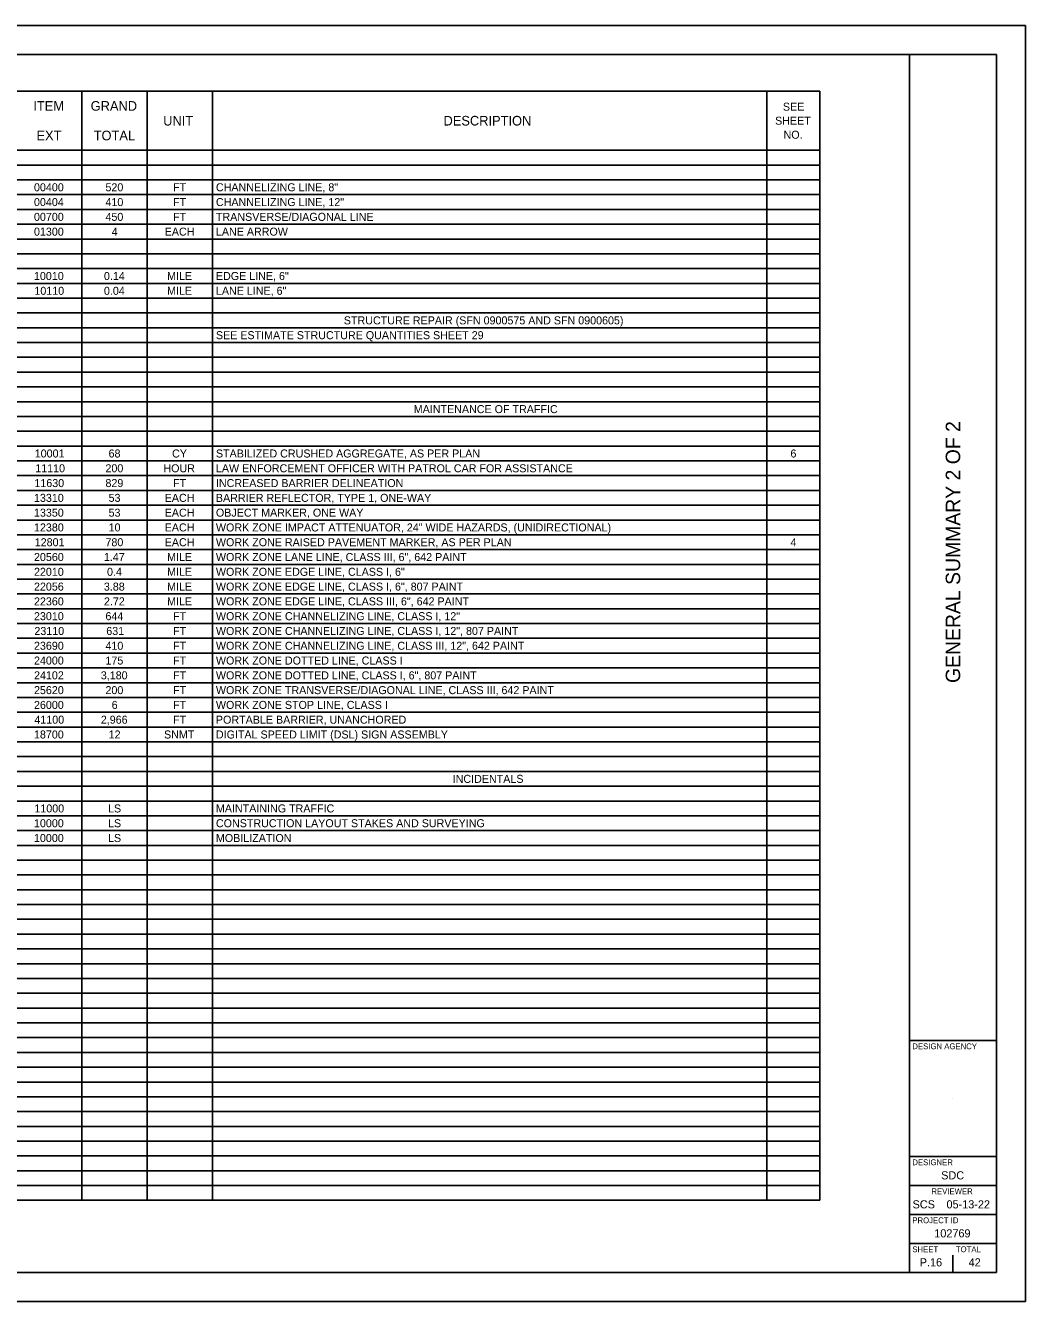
# Model space of a CAD drawing. Extents: x 0 to 34, y 0 to 22.
# Drawn here: x 16.76 to 34, y 0 to 22 of the extents above; entities that cross this region are included whole.
import ezdxf

# ---------------------------------------------------------------- set-up
doc = ezdxf.new("R2010")
doc.units = 0
for name, color, linetype in [('SH_Border', 7, 'Continuous'), ('SH_Cut_Line', 7, 'Continuous'), ('SH_Data', 7, 'Continuous'), ('SH_Text', 7, 'Continuous')]:
    doc.layers.add(name, color=color, linetype=linetype)

msp = doc.modelspace()

# ---------------------------------------------------------------- linework, layer by layer
at = {"layer": 'SH_Border'}
for p, q in [((32, 0.5), (32, 21.5)), ((32, 4.5), (33.5, 4.5)), ((32, 2.5), (33.5, 2.5)), ((32, 2), (33.5, 2)), ((32, 1.5), (33.5, 1.5)), ((32, 1), (33.5, 1))]:
    msp.add_line(p, q, dxfattribs=at)
msp.add_lwpolyline([(1.5, 21.5), (33.5, 21.5), (33.5, 0.5), (1.5, 0.5)], close=True, dxfattribs=at)
at = {"layer": 'SH_Cut_Line'}
msp.add_lwpolyline([(0, 0), (34, 0), (34, 22), (0, 22)], close=True, dxfattribs=at)
at = {"layer": 'SH_Data'}
for p, q in [((32.75, 3.5), (32.75, 3.5)), ((32.375, 0.675), (32.375, 0.675)), ((32.75, 0.5), (32.75, 0.8))]:
    msp.add_line(p, q, dxfattribs=at)
at = {"layer": 'SH_Text'}
for p, q in [((2.676, 20.869), (30.456, 20.869)), ((17.736, 20.869), (17.736, 1.744)), ((18.861, 20.869), (18.861, 1.744)), ((19.986, 20.869), (19.986, 1.744)), ((29.541, 20.869), (29.541, 1.744)), ((30.456, 20.869), (30.456, 1.744)), ((2.676, 19.849), (30.456, 19.849)), ((2.676, 19.594), (30.456, 19.594)), ((2.676, 19.339), (30.456, 19.339)), ((2.676, 19.084), (30.456, 19.084)), ((2.676, 18.829), (30.456, 18.829)), ((2.676, 18.574), (30.456, 18.574)), ((2.676, 18.319), (30.456, 18.319)), ((2.676, 18.064), (30.456, 18.064)), ((2.676, 17.809), (30.456, 17.809)), ((2.676, 17.554), (30.456, 17.554)), ((2.676, 17.299), (30.456, 17.299)), ((2.676, 17.044), (30.456, 17.044)), ((2.676, 16.789), (30.456, 16.789)), ((2.676, 16.534), (30.456, 16.534)), ((2.676, 16.279), (30.456, 16.279)), ((2.676, 16.024), (30.456, 16.024)), ((2.676, 15.769), (30.456, 15.769)), ((2.676, 15.514), (30.456, 15.514)), ((2.676, 15.259), (30.456, 15.259)), ((2.676, 15.004), (30.456, 15.004)), ((2.676, 14.749), (30.456, 14.749)), ((2.676, 14.494), (30.456, 14.494)), ((2.676, 14.239), (30.456, 14.239)), ((2.676, 13.984), (30.456, 13.984)), ((2.676, 13.729), (30.456, 13.729)), ((2.676, 13.474), (30.456, 13.474)), ((2.676, 13.219), (30.456, 13.219)), ((2.676, 12.964), (30.456, 12.964)), ((2.676, 12.709), (30.456, 12.709)), ((2.676, 12.454), (30.456, 12.454)), ((2.676, 12.199), (30.456, 12.199)), ((2.676, 11.944), (30.456, 11.944)), ((2.676, 11.689), (30.456, 11.689)), ((2.676, 11.434), (30.456, 11.434)), ((2.676, 11.179), (30.456, 11.179)), ((2.676, 10.924), (30.456, 10.924)), ((2.676, 10.669), (30.456, 10.669)), ((2.676, 10.414), (30.456, 10.414)), ((2.676, 10.159), (30.456, 10.159)), ((2.676, 9.904), (30.456, 9.904)), ((2.676, 9.649), (30.456, 9.649)), ((2.676, 9.394), (30.456, 9.394)), ((2.676, 9.139), (30.456, 9.139)), ((2.676, 8.884), (30.456, 8.884)), ((2.676, 8.629), (30.456, 8.629)), ((2.676, 8.374), (30.456, 8.374)), ((2.676, 8.119), (30.456, 8.119)), ((2.676, 7.864), (30.456, 7.864)), ((2.676, 7.609), (30.456, 7.609)), ((2.676, 7.354), (30.456, 7.354)), ((2.676, 7.099), (30.456, 7.099)), ((2.676, 6.844), (30.456, 6.844)), ((2.676, 6.589), (30.456, 6.589)), ((2.676, 6.334), (30.456, 6.334)), ((2.676, 6.079), (30.456, 6.079)), ((2.676, 5.824), (30.456, 5.824)), ((2.676, 5.569), (30.456, 5.569)), ((2.676, 5.314), (30.456, 5.314)), ((2.676, 5.059), (30.456, 5.059)), ((2.676, 4.804), (30.456, 4.804)), ((2.676, 4.549), (30.456, 4.549)), ((2.676, 4.294), (30.456, 4.294)), ((2.676, 4.039), (30.456, 4.039)), ((2.676, 3.784), (30.456, 3.784)), ((2.676, 3.529), (30.456, 3.529)), ((2.676, 3.274), (30.456, 3.274)), ((2.676, 3.019), (30.456, 3.019)), ((2.676, 2.764), (30.456, 2.764)), ((2.676, 2.509), (30.456, 2.509)), ((2.676, 2.254), (30.456, 2.254)), ((2.676, 1.999), (30.456, 1.999)), ((2.676, 1.744), (30.456, 1.744))]:
    msp.add_line(p, q, dxfattribs=at)

# ---------------------------------------------------------------- texts
at = {"layer": 'SH_Data'}
msp.add_text('GENERAL SUMMARY 2 OF 2', height=0.25, rotation=90, dxfattribs=at).set_placement((32.875, 10.664))
for s, height, p in [('DESIGN AGENCY', 0.1, (32.05, 4.35)), ('DESIGNER', 0.1, (32.05, 2.35)), ('SDC', 0.14, (32.547, 2.105)), ('REVIEWER', 0.1, (32.378, 1.85)), ('SCS', 0.14, (32.054, 1.605)), ('05-13-22', 0.14, (32.639, 1.605)), ('PROJECT ID', 0.1, (32.05, 1.35)), ('102769', 0.14, (32.428, 1.105)), ('SHEET', 0.1, (32.05, 0.85)), ('TOTAL', 0.1, (32.8, 0.85)), ('P.16', 0.14, (32.178, 0.605)), ('42', 0.14, (33.021, 0.605))]:
    msp.add_text(s, height=height, dxfattribs=at).set_placement(p)
at = {"layer": 'SH_Text'}
for s, height, p in [('ITEM', 0.1656, (16.899, 20.531)), ('GRAND', 0.1656, (17.887, 20.531)), ('SEE ', 0.138, (29.819, 20.531)), ('UNIT', 0.1656, (19.137, 20.276)), ('DESCRIPTION', 0.1656, (23.969, 20.276)), ('SHEET ', 0.138, (29.684, 20.29)), ('EXT', 0.1656, (16.953, 20.021)), ('TOTAL', 0.1656, (17.939, 20.021)), ('NO.', 0.138, (29.83, 20.048)), ('00400', 0.138, (16.91, 19.142)), ('520', 0.138, (18.142, 19.142)), ('FT', 0.138, (19.308, 19.142)), ('CHANNELIZING LINE, 8"', 0.138, (20.046, 19.142)), ('00404', 0.138, (16.91, 18.887)), ('410', 0.138, (18.142, 18.887)), ('FT', 0.138, (19.308, 18.887)), ('CHANNELIZING LINE, 12"', 0.138, (20.046, 18.887)), ('00700', 0.138, (16.91, 18.632)), ('450', 0.138, (18.142, 18.632)), ('FT', 0.138, (19.308, 18.632)), ('TRANSVERSE/DIAGONAL LINE', 0.138, (20.046, 18.632)), ('01300', 0.138, (16.91, 18.377)), ('4', 0.138, (18.25, 18.377)), ('EACH', 0.138, (19.163, 18.377)), ('LANE ARROW', 0.138, (20.046, 18.377)), ('10010', 0.138, (16.91, 17.612)), ('0.14', 0.138, (18.116, 17.612)), ('MILE', 0.138, (19.204, 17.612)), ('EDGE LINE, 6"', 0.138, (20.046, 17.612)), ('10110', 0.138, (16.917, 17.357)), ('0.04', 0.138, (18.116, 17.357)), ('MILE', 0.138, (19.204, 17.357)), ('LANE LINE, 6"', 0.138, (20.046, 17.357)), ('STRUCTURE REPAIR (SFN 0900575 AND SFN 0900605)', 0.138, (22.251, 16.847)), ('SEE ESTIMATE STRUCTURE QUANTITIES SHEET 29', 0.138, (20.046, 16.592)), ('MAINTENANCE OF TRAFFIC', 0.138, (23.456, 15.317)), ('10001', 0.138, (16.923, 14.552)), ('68', 0.138, (18.196, 14.552)), ('CY', 0.138, (19.29, 14.552)), ('STABILIZED CRUSHED AGGREGATE, AS PER PLAN', 0.138, (20.046, 14.552)), ('6', 0.138, (29.949, 14.552)), ('11110', 0.138, (16.932, 14.297)), ('200', 0.138, (18.142, 14.297)), ('HOUR', 0.138, (19.141, 14.297)), ('LAW ENFORCEMENT OFFICER WITH PATROL CAR FOR ASSISTANCE', 0.138, (20.046, 14.297)), ('11630', 0.138, (16.917, 14.042)), ('829', 0.138, (18.142, 14.042)), ('FT', 0.138, (19.308, 14.042)), ('INCREASED BARRIER DELINEATION', 0.138, (20.046, 14.042)), ('13310', 0.138, (16.91, 13.787)), ('53', 0.138, (18.196, 13.787)), ('EACH', 0.138, (19.163, 13.787)), ('BARRIER REFLECTOR, TYPE 1, ONE-WAY', 0.138, (20.046, 13.787)), ('13350', 0.138, (16.91, 13.532)), ('53', 0.138, (18.196, 13.532)), ('EACH', 0.138, (19.163, 13.532)), ('OBJECT MARKER, ONE WAY', 0.138, (20.046, 13.532)), ('WORK ZONE IMPACT ATTENUATOR, 24" WIDE HAZARDS, (UNIDIRECTIONAL)', 0.138, (20.046, 13.277)), ('12380', 0.138, (16.91, 13.277)), ('10', 0.138, (18.196, 13.277)), ('EACH', 0.138, (19.163, 13.277)), ('12801', 0.138, (16.923, 13.022)), ('780', 0.138, (18.142, 13.022)), ('EACH', 0.138, (19.163, 13.022)), ('WORK ZONE RAISED PAVEMENT MARKER, AS PER PLAN', 0.138, (20.046, 13.022)), ('4', 0.138, (29.95, 13.022)), ('20560', 0.138, (16.91, 12.767)), ('1.47', 0.138, (18.115, 12.767)), ('MILE', 0.138, (19.204, 12.767)), ('WORK ZONE LANE LINE, CLASS III, 6", 642 PAINT', 0.138, (20.046, 12.767)), ('22010', 0.138, (16.91, 12.512)), ('0.4', 0.138, (18.169, 12.512)), ('MILE', 0.138, (19.204, 12.512)), ('WORK ZONE EDGE LINE, CLASS I, 6"', 0.138, (20.046, 12.512)), ('22056', 0.138, (16.91, 12.257)), ('3.88', 0.138, (18.115, 12.257)), ('MILE', 0.138, (19.204, 12.257)), ('WORK ZONE EDGE LINE, CLASS I, 6", 807 PAINT', 0.138, (20.046, 12.257)), ('22360', 0.138, (16.91, 12.002)), ('2.72', 0.138, (18.116, 12.002)), ('MILE', 0.138, (19.204, 12.002)), ('WORK ZONE EDGE LINE, CLASS III, 6", 642 PAINT', 0.138, (20.046, 12.002)), ('23010', 0.138, (16.91, 11.747)), ('644', 0.138, (18.142, 11.747)), ('FT', 0.138, (19.308, 11.747)), ('WORK ZONE CHANNELIZING LINE, CLASS I, 12"', 0.138, (20.046, 11.747)), ('23110', 0.138, (16.917, 11.492)), ('631', 0.138, (18.156, 11.492)), ('FT', 0.138, (19.308, 11.492)), ('WORK ZONE CHANNELIZING LINE, CLASS I, 12", 807 PAINT', 0.138, (20.046, 11.492)), ('23690', 0.138, (16.91, 11.237)), ('410', 0.138, (18.142, 11.237)), ('FT', 0.138, (19.308, 11.237)), ('WORK ZONE CHANNELIZING LINE, CLASS III, 12", 642 PAINT', 0.138, (20.046, 11.237)), ('24000', 0.138, (16.91, 10.982)), ('175', 0.138, (18.142, 10.982)), ('FT', 0.138, (19.308, 10.982)), ('WORK ZONE DOTTED LINE, CLASS I', 0.138, (20.046, 10.982)), ('24102', 0.138, (16.911, 10.727)), ('3,180', 0.138, (18.062, 10.727)), ('FT', 0.138, (19.308, 10.727)), ('WORK ZONE DOTTED LINE, CLASS I, 6", 807 PAINT', 0.138, (20.046, 10.727)), ('25620', 0.138, (16.91, 10.472)), ('200', 0.138, (18.142, 10.472)), ('FT', 0.138, (19.308, 10.472)), ('WORK ZONE TRANSVERSE/DIAGONAL LINE, CLASS III, 642 PAINT', 0.138, (20.046, 10.472)), ('26000', 0.138, (16.91, 10.217)), ('6', 0.138, (18.249, 10.217)), ('FT', 0.138, (19.308, 10.217)), ('WORK ZONE STOP LINE, CLASS I', 0.138, (20.046, 10.217)), ('41100', 0.138, (16.917, 9.962)), ('2,966', 0.138, (18.062, 9.962)), ('FT', 0.138, (19.308, 9.962)), ('PORTABLE BARRIER, UNANCHORED', 0.138, (20.046, 9.962)), ('18700', 0.138, (16.91, 9.707)), ('12', 0.138, (18.197, 9.707)), ('SNMT', 0.138, (19.152, 9.707)), ('DIGITAL SPEED LIMIT (DSL) SIGN ASSEMBLY', 0.138, (20.046, 9.707)), ('INCIDENTALS', 0.138, (24.127, 8.942)), ('11000', 0.138, (16.917, 8.432)), ('LS', 0.138, (18.186, 8.432)), ('MAINTAINING TRAFFIC', 0.138, (20.046, 8.432)), ('10000', 0.138, (16.91, 8.177)), ('LS', 0.138, (18.186, 8.177)), ('CONSTRUCTION LAYOUT STAKES AND SURVEYING', 0.138, (20.046, 8.177)), ('10000', 0.138, (16.91, 7.922)), ('LS', 0.138, (18.186, 7.922)), ('MOBILIZATION', 0.138, (20.046, 7.922))]:
    msp.add_text(s, height=height, dxfattribs=at).set_placement(p)

doc.saveas('drawing.dxf')
